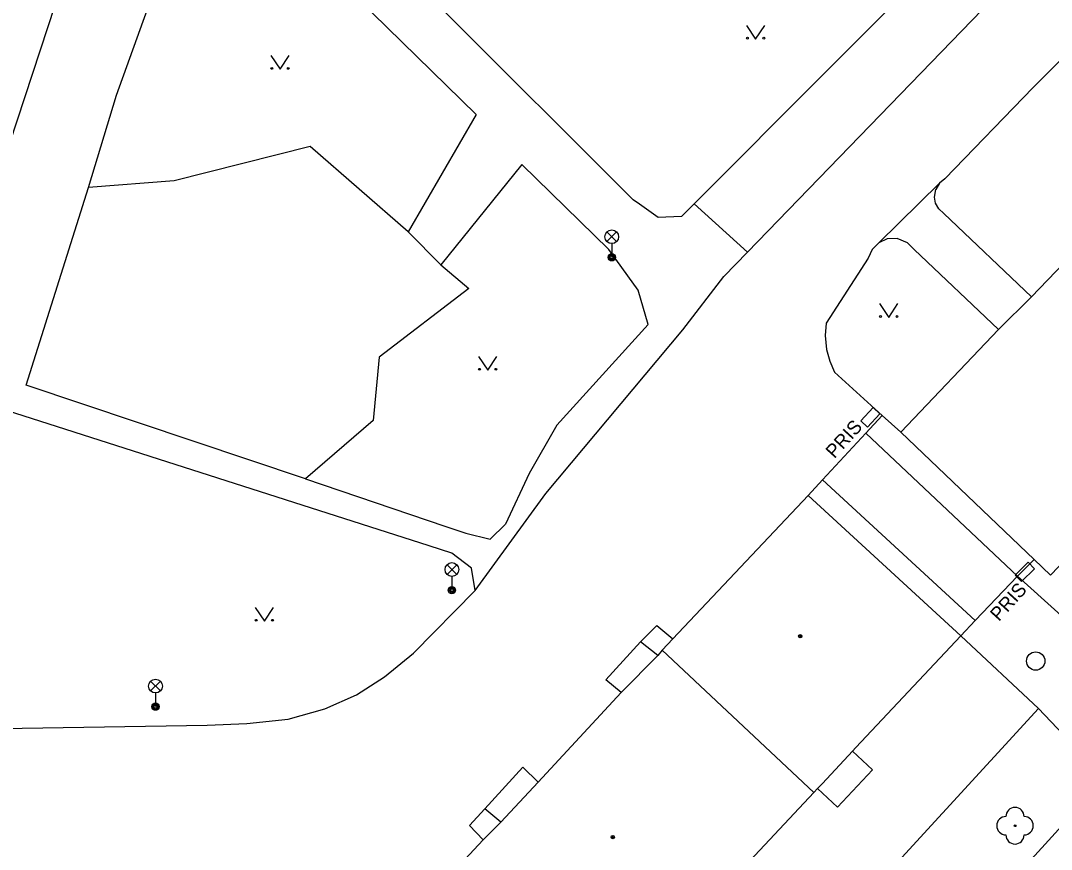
# Model space of a CAD drawing. Extents: x -598932 to -598196, y -1162207 to -1161504.
# Drawn here: x -598603.5 to -598547.1, y -1161700 to -1161654.7 of the extents above; entities that cross this region are included whole.
import ezdxf

# ---------------------------------------------------------------- set-up
doc = ezdxf.new("R2010")
doc.units = 0
for name, color, linetype in [('Level 22', 7, 'Continuous'), ('Level 24', 7, 'Continuous'), ('Level 27', 7, 'Continuous'), ('Level 33', 7, 'Continuous'), ('Level 36', 7, 'Continuous'), ('Level 39', 7, 'Continuous'), ('specificka linie pasportu komunikaci', 7, 'Continuous'), ('TM - budovy zdene_ betonove - NP', 7, 'Continuous'), ('TM - budovy zdene_ betonove - VP', 7, 'Continuous'), ('TM - chodniky - VP', 7, 'Continuous'), ('TM - komunikace - VP', 7, 'Continuous'), ('TM - letecke snimky - pomocna linie', 7, 'Continuous'), ('TM - popis objektu', 7, 'Continuous'), ('TM - rozhrani ploch obecne - VP', 7, 'Continuous')]:
    doc.layers.add(name, color=color, linetype=linetype)

msp = doc.modelspace()

# ---------------------------------------------------------------- linework, layer by layer
at = {"layer": 'Level 22'}
msp.add_circle((-598549.12, -1161698.73), 0.05, dxfattribs=at)
for centre, start, end in [((-598549.12, -1161698.23), 0, 180), ((-598549.62, -1161698.73), 90, 270), ((-598548.62, -1161698.73), 270, 90), ((-598549.12, -1161699.23), 180, 0)]:
    msp.add_arc(centre, 0.5, start, end, dxfattribs=at)
at = {"layer": 'Level 24'}
for points in [[(-598557.188, -1161676.946), (-598556.506, -1161676.214), (-598556.872, -1161675.874), (-598557.554, -1161676.605)], [(-598548.762, -1161685.389), (-598548.048, -1161684.688), (-598548.398, -1161684.331), (-598549.112, -1161685.032)]]:
    msp.add_lwpolyline(points, close=True, dxfattribs=at)
at = {"layer": 'Level 27'}
msp.add_circle((-598547.99, -1161689.73), 0.5, dxfattribs=at)
at = {"layer": 'Level 33'}
for p, q in [((-598571.425, -1161666.8), (-598570.895, -1161666.27)), ((-598571.425, -1161666.27), (-598570.895, -1161666.8)), ((-598571.16, -1161666.91), (-598571.16, -1161667.66)), ((-598580.165, -1161684.99), (-598579.635, -1161684.46)), ((-598580.165, -1161684.46), (-598579.635, -1161684.99)), ((-598579.9, -1161685.1), (-598579.9, -1161685.85)), ((-598596.365, -1161691.36), (-598595.835, -1161690.83)), ((-598596.365, -1161690.83), (-598595.835, -1161691.36)), ((-598596.1, -1161691.47), (-598596.1, -1161692.22))]:
    msp.add_line(p, q, dxfattribs=at)
for centre, radius in [((-598571.16, -1161666.535), 0.375), ((-598571.16, -1161667.66), 0.2), ((-598571.16, -1161667.66), 0.145), ((-598571.16, -1161667.66), 0.0876), ((-598579.9, -1161684.725), 0.375), ((-598579.9, -1161685.85), 0.2), ((-598579.9, -1161685.85), 0.145), ((-598579.9, -1161685.85), 0.0876), ((-598596.1, -1161691.095), 0.375), ((-598596.1, -1161692.22), 0.2), ((-598596.1, -1161692.22), 0.145), ((-598596.1, -1161692.22), 0.0876)]:
    msp.add_circle(centre, radius, dxfattribs=at)
at = {"layer": 'Level 36'}
for points in [[(-598563.8, -1161654.98), (-598563.3, -1161655.73), (-598562.8, -1161654.98)], [(-598589.79, -1161656.63), (-598589.29, -1161657.38), (-598588.79, -1161656.63)], [(-598556.52, -1161670.19), (-598556.02, -1161670.94), (-598555.52, -1161670.19)], [(-598578.44, -1161673.08), (-598577.94, -1161673.83), (-598577.44, -1161673.08)], [(-598590.65, -1161686.8), (-598590.15, -1161687.55), (-598589.65, -1161686.8)]]:
    msp.add_lwpolyline(points, dxfattribs=at)
for centre in [(-598563.75, -1161655.68), (-598562.851, -1161655.68), (-598589.74, -1161657.33), (-598588.841, -1161657.33), (-598556.47, -1161670.89), (-598555.571, -1161670.89), (-598578.39, -1161673.78), (-598577.491, -1161673.78), (-598590.6, -1161687.5), (-598589.701, -1161687.5)]:
    msp.add_circle(centre, 0.05, dxfattribs=at)
at = {"layer": 'Level 39'}
for centre, radius in [((-598560.86, -1161688.37), 0.09), ((-598560.86, -1161688.37), 0.0398), ((-598571.11, -1161699.35), 0.09), ((-598571.11, -1161699.35), 0.0398)]:
    msp.add_circle(centre, radius, dxfattribs=at)
at = {"layer": 'specificka linie pasportu komunikaci'}
for points in [[(-598563.74, -1161667.369), (-598548.126, -1161651.231)], [(-598556.57, -1161666.86), (-598553.24, -1161663.61)], [(-598563.74, -1161667.369), (-598566.651, -1161664.728)], [(-598574.762, -1161680.572), (-598567.277, -1161671.622), (-598565.034, -1161668.706), (-598563.74, -1161667.369)], [(-598559.647, -1161679.828), (-598551.29, -1161687.51)], [(-598578.63, -1161685.88), (-598574.762, -1161680.572)], [(-598548.99, -1161685.08), (-598544.76, -1161688.89)], [(-598552.08, -1161688.35), (-598547.84, -1161692.32)], [(-598559.91, -1161696.69), (-598558.821, -1161697.718), (-598556.904, -1161695.677), (-598558, -1161694.65)]]:
    msp.add_lwpolyline(points, dxfattribs=at)
at = {"layer": 'TM - budovy zdene_ betonove - NP'}
for points in [[(-598548.99, -1161685.08), (-598557.27, -1161677.27)], [(-598552.08, -1161688.35), (-598560.43, -1161680.67)]]:
    msp.add_lwpolyline(points, dxfattribs=at)
at = {"layer": 'TM - budovy zdene_ betonove - VP'}
for points in [[(-598543.36, -1161664.75), (-598548.22, -1161669.81)], [(-598548.22, -1161669.81), (-598550.02, -1161671.6)], [(-598550.02, -1161671.6), (-598555.37, -1161677.21)], [(-598535.07, -1161672.42), (-598547.18, -1161685.03)], [(-598556.38, -1161676.31), (-598557.27, -1161677.27)], [(-598555.37, -1161677.21), (-598556.38, -1161676.31)], [(-598557.27, -1161677.27), (-598559.647, -1161679.828), (-598560.43, -1161680.67)], [(-598555.37, -1161677.21), (-598548.07, -1161684.17)], [(-598560.43, -1161680.67), (-598567.83, -1161688.52)], [(-598548.07, -1161684.17), (-598548.99, -1161685.08)], [(-598547.18, -1161685.03), (-598548.07, -1161684.17)], [(-598548.99, -1161685.08), (-598551.29, -1161687.51), (-598552.08, -1161688.35)], [(-598552.08, -1161688.35), (-598557.82, -1161694.46)], [(-598567.83, -1161688.52), (-598568.4, -1161689.13)], [(-598568.65, -1161689.42), (-598570.65, -1161691.44)], [(-598568.4, -1161689.13), (-598568.65, -1161689.42)], [(-598568.4, -1161689.13), (-598560.12, -1161696.91)], [(-598570.65, -1161691.44), (-598575.19, -1161696.34)], [(-598557.82, -1161694.46), (-598558, -1161694.65), (-598559.65, -1161696.42)], [(-598575.19, -1161696.34), (-598577.23, -1161698.53)], [(-598559.65, -1161696.42), (-598559.91, -1161696.69), (-598560.12, -1161696.91)], [(-598560.12, -1161696.91), (-598571.95, -1161709.54)], [(-598577.23, -1161698.53), (-598578.19, -1161699.5)], [(-598578.19, -1161699.5), (-598580.2, -1161701.65)]]:
    msp.add_lwpolyline(points, dxfattribs=at)
at = {"layer": 'TM - chodniky - VP'}
for points in [[(-598569.65, -1161664.76), (-598570, -1161664.51), (-598580.5, -1161654.03), (-598587.8, -1161647.5), (-598593.83, -1161644.24)], [(-598591.94, -1161648.56), (-598585.06, -1161653.5), (-598578.58, -1161659.86)], [(-598599.77, -1161663.85), (-598598.24, -1161658.79), (-598595.24, -1161650.49)], [(-598567.35, -1161665.43), (-598566.651, -1161664.728), (-598552.3, -1161650.32)], [(-598545.02, -1161655.24), (-598548.13, -1161658.38), (-598552.96, -1161663.37), (-598553.24, -1161663.61), (-598553.45, -1161663.96)], [(-598578.58, -1161659.86), (-598582.29, -1161666.26)], [(-598582.29, -1161666.26), (-598587.65, -1161661.6), (-598595.08, -1161663.48)], [(-598571.18, -1161667.44), (-598571.33, -1161667.24), (-598576.07, -1161662.58), (-598580.5, -1161668.07)], [(-598595.08, -1161663.48), (-598599.77, -1161663.85)], [(-598548.22, -1161669.81), (-598553.01, -1161665.26), (-598553.29, -1161665.01), (-598553.46, -1161664.69), (-598553.52, -1161664.38), (-598553.45, -1161663.96)], [(-598567.35, -1161665.43), (-598568.62, -1161665.49), (-598569.65, -1161664.76)], [(-598556.1, -1161666.65), (-598556.57, -1161666.86), (-598556.93, -1161667.23), (-598557.14, -1161667.71), (-598559.44, -1161671.26), (-598559.49, -1161671.94), (-598559.43, -1161672.7), (-598559.25, -1161673.34), (-598558.99, -1161673.94), (-598556.38, -1161676.31)], [(-598550.02, -1161671.6), (-598554.64, -1161667.24), (-598555, -1161666.87), (-598555.57, -1161666.63), (-598556.1, -1161666.65)], [(-598569.17, -1161671.33), (-598569.72, -1161669.45), (-598571.18, -1161667.44)], [(-598580.5, -1161668.07), (-598578.97, -1161669.37), (-598583.88, -1161673.11), (-598584.21, -1161676.58), (-598587.9, -1161679.77)], [(-598569.17, -1161671.33), (-598574.16, -1161676.83), (-598575.68, -1161679.47), (-598576.97, -1161682.25)], [(-598581.15, -1161683.43), (-598604.25, -1161676.04)], [(-598587.9, -1161679.77), (-598580.29, -1161682.35)], [(-598580.29, -1161682.35), (-598579.13, -1161682.74), (-598577.81, -1161683.07), (-598576.97, -1161682.25)], [(-598578.63, -1161685.88), (-598578.82, -1161684.65), (-598579.9, -1161683.83), (-598581.15, -1161683.43)], [(-598581.99, -1161689.3), (-598578.63, -1161685.88)], [(-598583.59, -1161690.6), (-598581.99, -1161689.3)], [(-598591.1, -1161693.15), (-598588.85, -1161692.9), (-598586.84, -1161692.34), (-598585.12, -1161691.58), (-598583.59, -1161690.6)], [(-598546.13, -1161694.12), (-598547.84, -1161692.32), (-598560.75, -1161706.41), (-598575.56, -1161722.59)], [(-598610.15, -1161693.51), (-598593.28, -1161693.23)], [(-598593.28, -1161693.23), (-598591.1, -1161693.15)]]:
    msp.add_lwpolyline(points, dxfattribs=at)
at = {"layer": 'TM - komunikace - VP'}
msp.add_lwpolyline([(-598546.02, -1161698.14), (-598562.51, -1161716.26), (-598574.19, -1161724.71)], dxfattribs=at)
at = {"layer": 'TM - letecke snimky - pomocna linie'}
for points in [[(-598606.584, -1161669.015), (-598599.9, -1161648.76)], [(-598587.9, -1161679.77), (-598603.178, -1161674.653), (-598599.77, -1161663.85)], [(-598582.29, -1161666.26), (-598580.5, -1161668.07)]]:
    msp.add_lwpolyline(points, dxfattribs=at)
at = {"layer": 'TM - rozhrani ploch obecne - VP'}
for points in [[(-598569.6, -1161688.67), (-598568.69, -1161687.79), (-598567.83, -1161688.52)], [(-598570.65, -1161691.44), (-598571.48, -1161690.75), (-598569.6, -1161688.67)], [(-598568.65, -1161689.42), (-598569.6, -1161688.67)], [(-598578.1, -1161697.81), (-598576.02, -1161695.52), (-598575.19, -1161696.34)], [(-598578.19, -1161699.5), (-598578.94, -1161698.71), (-598578.1, -1161697.81)], [(-598577.23, -1161698.53), (-598578.1, -1161697.81)]]:
    msp.add_lwpolyline(points, dxfattribs=at)

# ---------------------------------------------------------------- texts
at = {"layer": 'TM - popis objektu'}
for p in [(-598558.99, -1161678.7), (-598550, -1161687.6)]:
    msp.add_text('PRIS', height=0.75, rotation=47.73, dxfattribs=at).set_placement(p)

doc.saveas('drawing.dxf')
